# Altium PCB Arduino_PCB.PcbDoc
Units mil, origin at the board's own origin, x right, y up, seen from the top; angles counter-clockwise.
Board outline 2700 x 2100 mil, 2 copper layers (Top Layer, Bottom Layer), stack 44.685 mil thick; 55 components, 50 nets, 239 pads, 59 vias.
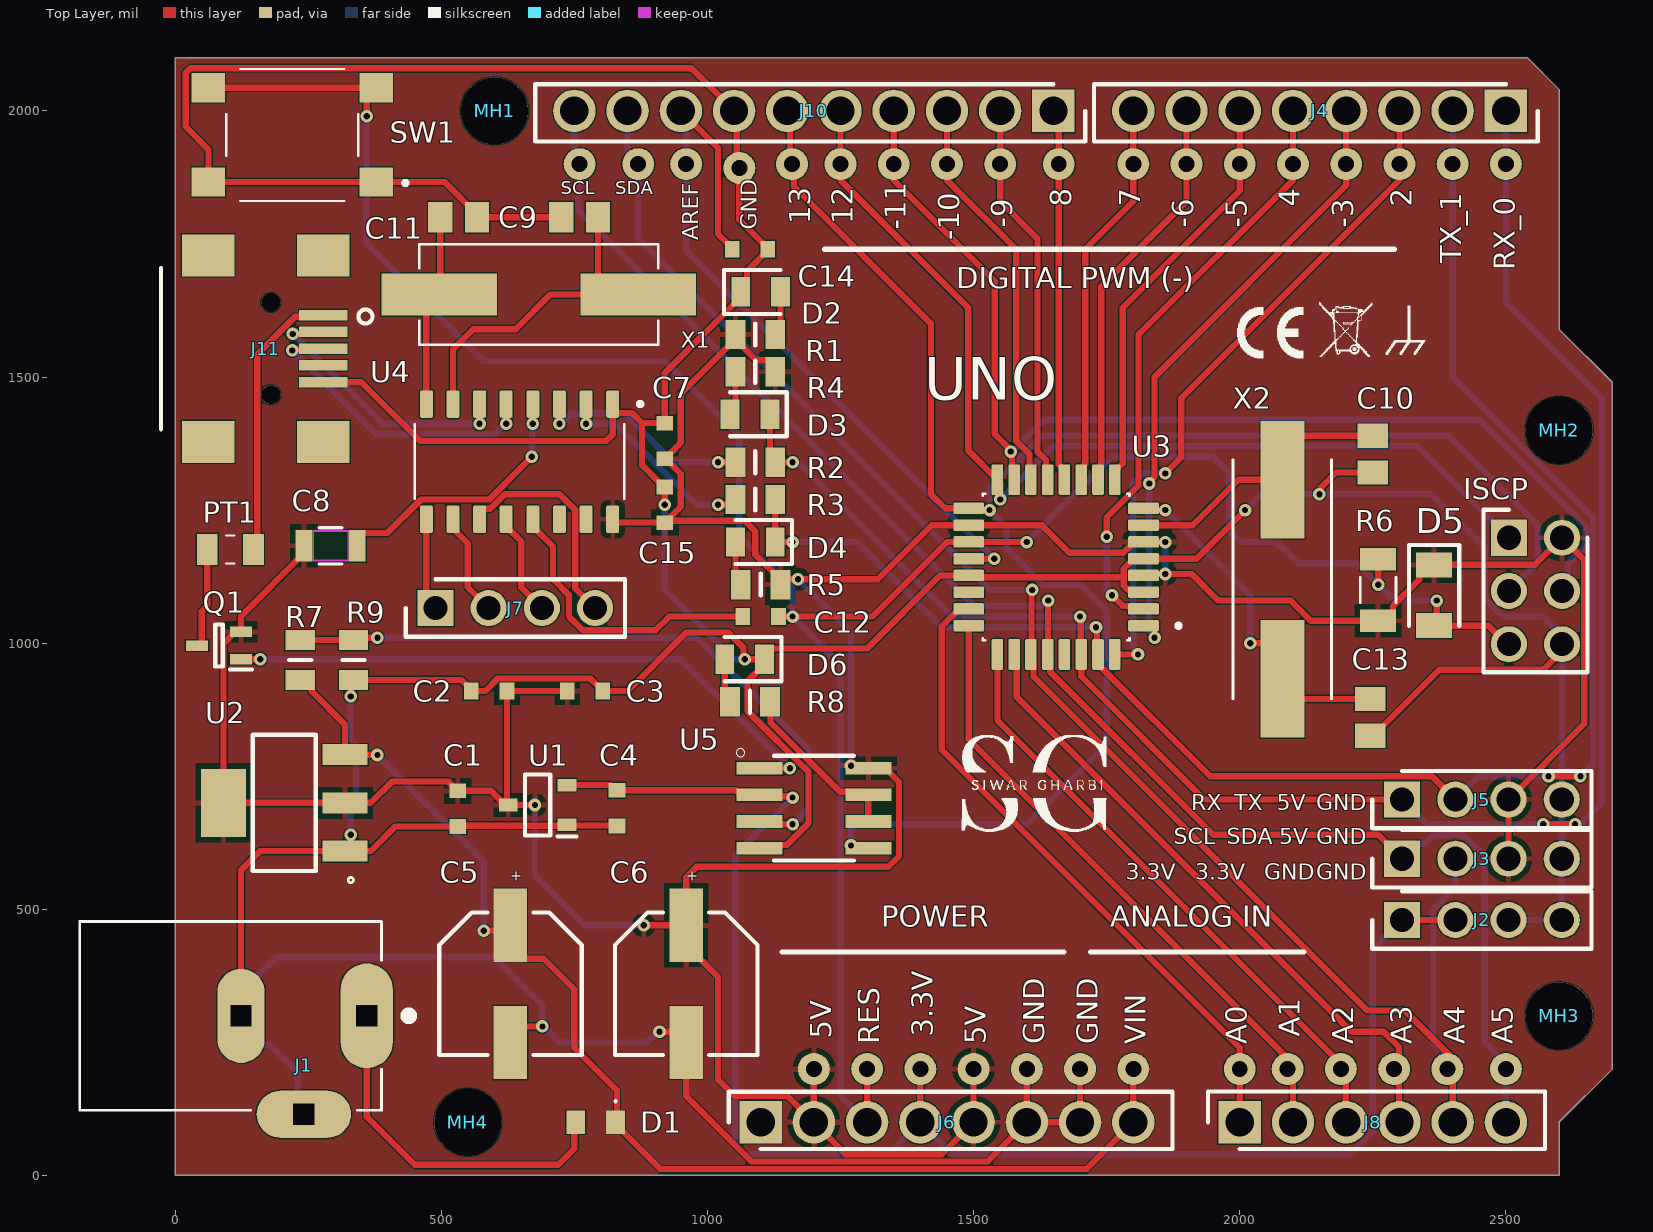
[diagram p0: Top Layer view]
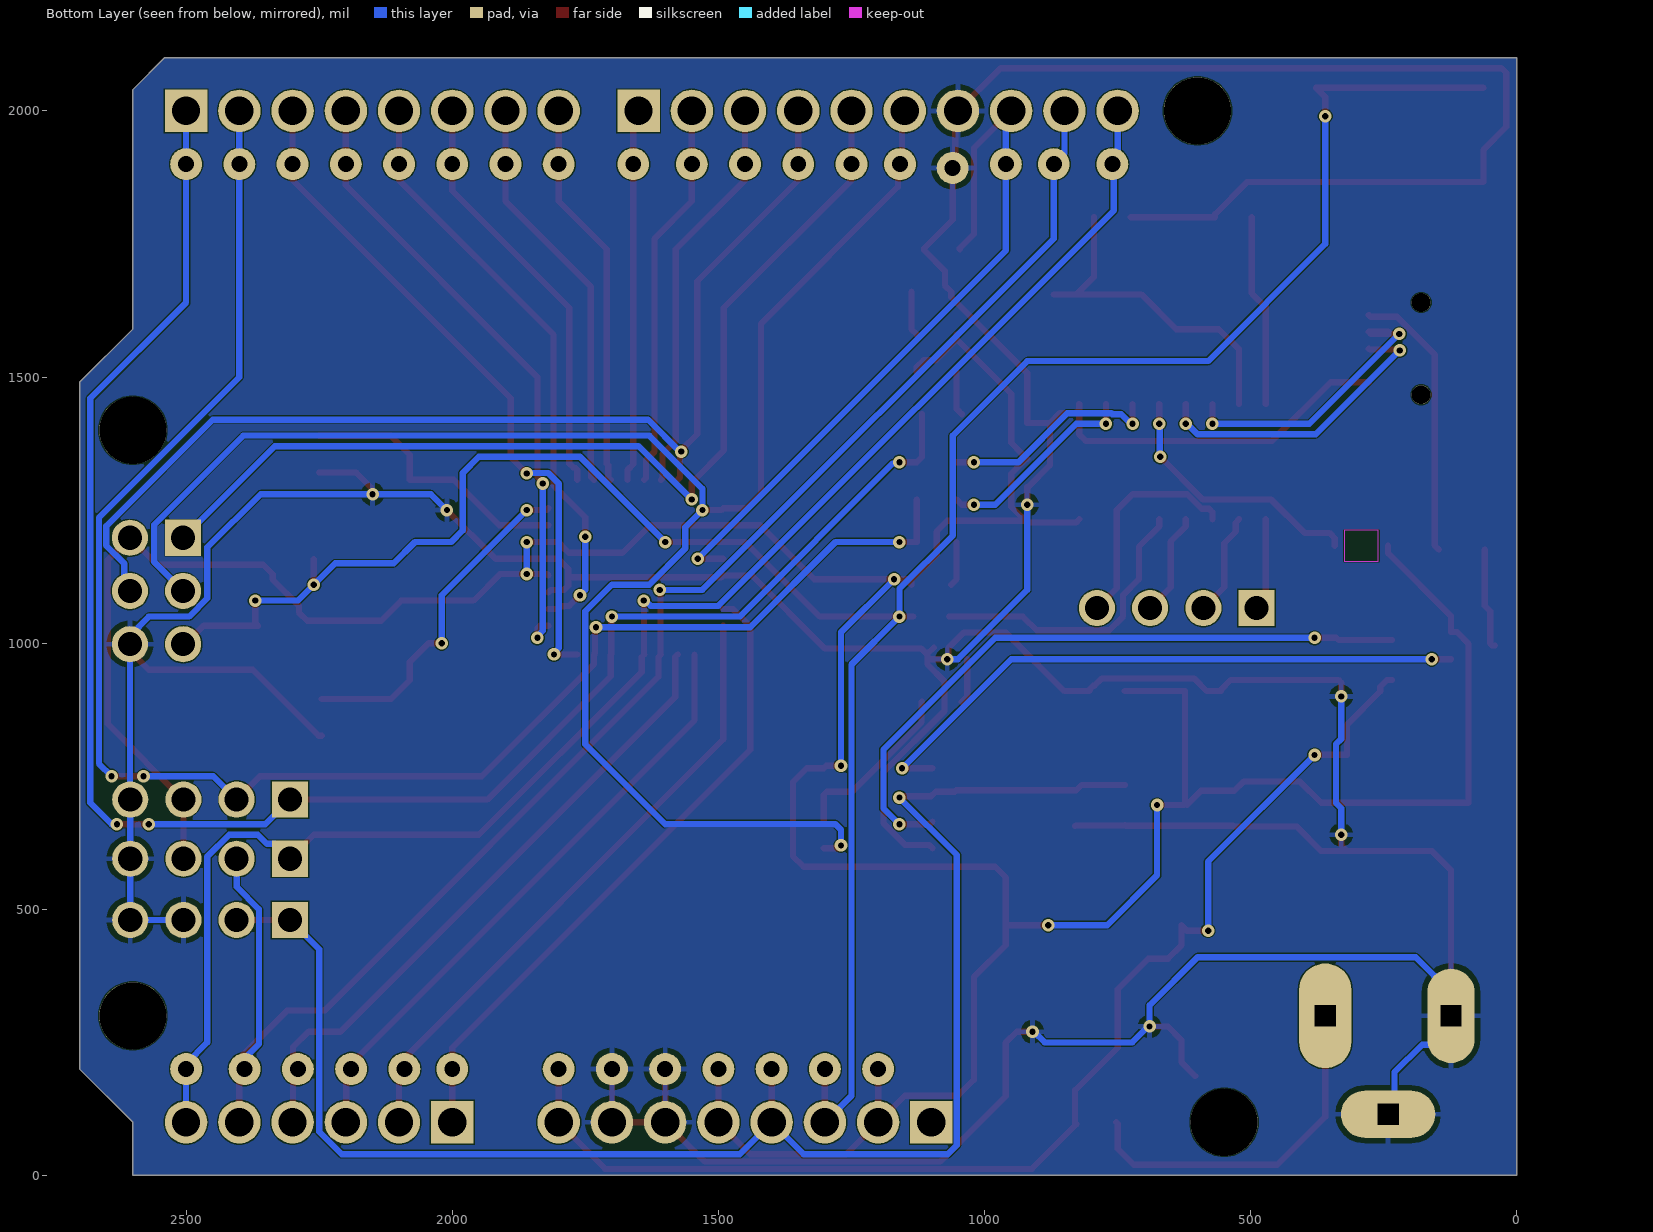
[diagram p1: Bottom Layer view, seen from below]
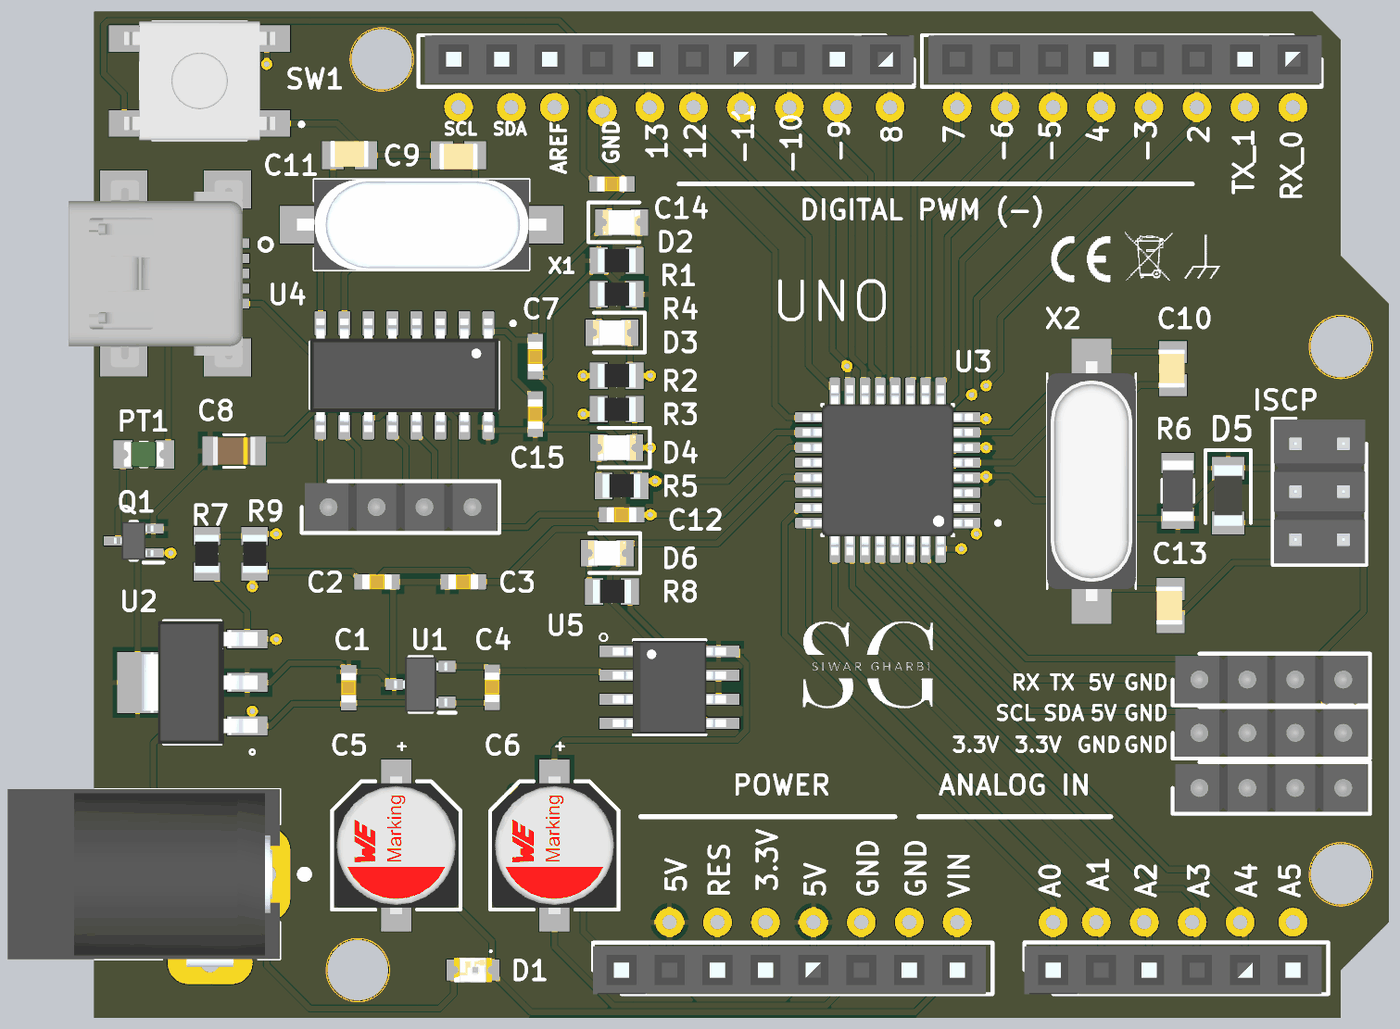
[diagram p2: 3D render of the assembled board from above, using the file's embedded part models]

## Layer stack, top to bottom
Top Solder: solder mask 62.992, SM-001, Dk 4
Top Layer: signal copper 1.378
Dielectric 2: core 41.929, FR-4, Dk 4.8
Bottom Layer: signal copper 1.378
Bottom Solder: solder mask 62.992, SM-001, Dk 4

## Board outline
0,0 2600,0 2600,100 2700,200 2700,1490 2600,1590 2600,2040 2540,2100 0,2100

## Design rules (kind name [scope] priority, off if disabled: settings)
Clearance [All] p1: gap=2 ignorepadtopadclearanceinfootprint=FALSE
ComponentClearance [All] p1: gap=3.94 collisioncheckmode=3 verticalgap=7.87 showdistances=FALSE
HoleSize [All] p1: absolutevalues=TRUE maxlimit=138 minlimit=7.87 maxpercent=80.000 minpercent=20.000
HoleToHoleClearance [All] p1: gap=11.81 allowstackedmicrovias=TRUE
MinimumSolderMaskSliver [All] p1: minsoldermaskwidth=0.07
PolygonConnect [All] p1: connectstyle=Relief reliefconductorwidth=10 reliefentries=4 polygonreliefangle="90 Angle" airgapwidth=10
RoutingVias [All] p1: holewidth=11.81 width=23.62 viastyle="Through Hole" minholewidth=11.81 minwidth=23.62 maxholewidth=11.81 maxwidth=23.62
SilkToSilkClearance [All] p1: silktosilkclearance=0
SilkToSolderMaskClearance [IsPad] p1: minsilkscreentomaskgap=0 clearancetoexposedcopper=TRUE
SolderMaskExpansion [All] p1: expansion=1.5 istentingtop=FALSE
Width [All] p1: maxlimit=39.37 minlimit=11.81 preferedwidth=11.81
24 further rules are at their usual default settings.

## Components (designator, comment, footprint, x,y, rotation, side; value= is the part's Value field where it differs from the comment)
C1 "100nF" WCAP-CSGP_0603_L1.6W0.8H0.8_Wave 531,689.11 r90 top
C2 "100nF" WCAP-CSGP_0603_L1.6W0.8H0.8_Wave 590,910 r0 top
C3 "100nF" WCAP-CSGP_0603_L1.6W0.8H0.8_Wave 770,910 r0 top
C4 "100nF" WCAP-CSGP_0603_L1.6W0.8H0.8_Wave 830,690 r90 top
C5 "47uF" WCAP-ASLI_D6.3H7.7 630,360 r90 top
C6 "47uF" WCAP-ASLI_D6.3H7.7 960,360 r90 top
C7 "100nF" WCAP-CSGP_0603_L1.6W0.8H0.8_Wave 920,1380 r90 top
C8 "10n" CAP_C0805_VEN-M 292,1183 r180 top
C9 "22pF" CAPC2012X140N 760,1800 r0 top
C10 "22pF" CAPC2012X140N 2250,1355 r270 top
C11 "22pF" CAPC2012X140N 532.55,1800 r180 top
C12 "100nF" WCAP-CSGP_0603_L1.6W0.8H0.8_Wave 1100,1050 r0 top
C13 "22pF" CAPC2012X140N 2245,860.55 r270 top
C14 "100nF" WCAP-CSGP_0603_L1.6W0.8H0.8_Wave 1080,1740 r0 top
C15 "100nF" WCAP-CSGP_0603_L1.6W0.8H0.8_Wave 920,1260 r270 top
D1 "Infrared, 1.4V, 140°" WL-SICW_0805_L2W1.3H0.8 790,100 r180 top
D2 "Green LED" LEDC2012X80N 1100,1660 r0 top
D3 "Green LED" LEDC2012X80N 1080,1430 r180 top
D4 "Green LED" LEDC2012X80N 1090,1190 r180 top
D5 "CD1206-S01575" DIOC3215X95N 2365,1090 r270 top
D6 "Green LED" LEDC2012X80N 1070,970 r180 top
ISCP "3X2 Male" HDRV6W67P254_2X3_762X483X858P 2505.51,1198.1 r270 top (schematic designator J9)
J1 "PJ-002A" CUI_PJ-002A 360,300 r180 top locked
J2 "4X1_Male" HDRV4W95P0X254_1X4_1016X254X854P 2305,480 r0 top
J3 "4X1_Male" HDRV4W95P0X254_1X4_1016X254X854P 2305,595 r0 top
J4 "8X1 Female" RHDR8W80P0X254_1X8_2082X254X850P 2500,2000 r180 top
J5 "4X1_Male" HDRV4W95P0X254_1X4_1016X254X854P 2305,706.18 r0 top
J6 "8X1 Female" RHDR8W80P0X254_1X8_2082X254X850P 1100,100 r0 top
J7 "4X1_Male" HDRV4W95P0X254_1X4_1016X254X854P 489,1066 r0 top
J8 "6X1 Female" RHDR6W80P0X254_1X6_1574X254X870P 2000,100 r0 top
J10 "10X1 Female" RHDR10W80P0X254_1X10_2590X254X850P 1650,2000 r180 top
J11 "USB Connector" 1734035-2USB 180,1466.77 r0 top
MH1 "MH_NP_3.2mm" MH_NP_3.2mm#1 600,1980 r0 top
MH2 "MH_NP_3.2mm" MH_NP_3.2mm#2 2600,1400 r0 top
MH3 "MH_NP_3.2mm" MH_NP_3.2mm#2 2600,300 r0 top
MH4 "MH_NP_3.2mm" MH_NP_3.2mm#2 550,100 r0 top
PT1 "500mA" 0ZCK0050AF2E 103.69,1176 r180 top
Q1 "SI1317DL-T1-GE3" SOT65P210X110-3N 82.44,995.59 r180 top
R1 "1K" RESC2012X60N 1090,1580 r0 top
R2 "1K" RESC2012X60N 1090,1340 r0 top
R3 "1K" RESC2012X60N 1090,1270 r0 top
R4 "1K" RESC2012X60N 1090,1510 r180 top
R5 "1K" RESC2012X60N 1100,1110 r180 top
R6 "10 Ohm" RESC3216X70N 2260,1100 r270 top
R7 "10K" RESC2012X60N 235,968.4 r90 top
R8 "1K" RESC2012X60N 1080,890 r180 top
R9 "10K" RESC2012X60N 335,968.4 r90 top
SW1 "B3FS-1000" B3FS1000 220,1955 r0 top
U1 "XC6206P332MR-G" SOT95P280X130-3N 681,696 r180 top
U2 "NCP1117ST50T3G" SOT230P700X180-4N 205,700 r180 top
U3 "ATMEGA328P-AU" QFP80P900X900X120-32N 1655,1143 r180 top
U4 "CH340G" SOIC127P600X180-16N 647,1341 r270 top
U5 "LM358DR2G" SOIC127P600X175-8N 1200,690 r0 top
X1 "12MHz" XTAL_ECS-120-S-5PX-TR 682.99,1655 r180 top
X2 "16MHZ" XTAL_ABLS-9.216MHZ-B4-T 2080,1120 r270 top

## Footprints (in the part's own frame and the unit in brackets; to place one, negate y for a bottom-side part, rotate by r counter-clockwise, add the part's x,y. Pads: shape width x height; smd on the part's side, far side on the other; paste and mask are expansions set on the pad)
0ZCK0050AF2E [mm]
  rect 1x1.5 smd: 1(-1.1,0) 2(1.1,0)
  silkscreen extent -0.2,-0.67 0.2,0.67, body extent -1.07,-0.67 1.07,0.67, height 1.26
1734035-2USB [mm]
  rect 2.3x0.5 smd: 1(2.5,3.8) 2(2.5,3) 3(2.5,2.2) 4(2.5,1.4) 5(2.5,0.6)
  rect 2.5x2 smd: 6(2.5,-2.25) 7(-3,-2.25) 8(-3,6.65) 9(2.5,6.65)
  round 0.9 hole 0.9 unplated: 10(0,4.4) 11(0,0)
  silkscreen extent -5.25,-1.65 4.85,6.05, body extent -5.89,-2.76 3.31,7.14, height 4.14
B3FS1000 [mm]
  rect 1.6x1.4 smd: 1(4,-2.25) 2(-4,-2.25) 3(4,2.25) 4(-4,2.25)
  silkscreen extent -3.15,-3.15 5.5,3.15, body extent -4,-3.15 4,3.15, height 3
CAP_C0805_VEN-M [mil]
  rect 32x60 smd paste+0 mask+0: 1(-50,0) 2(50,0)
  Top Layer keep-out region: -32,-27 -32,27 32,27 32,-27
  Keep-Out Layer region: -32,-29 -32,29 32,29 32,-29
  silkscreen extent -22,-34 22,34, body extent -44,-29 44,29, height 12
CAPC2012X140N [mm]
  rect 1.16x1.47 smd: 1(-0.875,0) 2(0.875,0)
  body extent -1.02,-0.76 1.02,0.64, height 1.28
CUI_PJ-002A [mm]
  oval 2.5x5 hole 1 square: 1(0,0)
  oval 2.25x4.5 hole 1 square: 2(6,0)
  oval 4.5x2.25 hole 1 square: 3(3,4.7)
  silkscreen extent -2.2,-4.5 13.7,4.5, body extent -0.7,-4.5 13.7,4.9, height 11
DIOC3215X95N [mm]
  rect 1.2x1.7 smd: 1(-1.45,0) 2(1.45,0)
  silkscreen extent -2.4,-1.2 1.45,1.2, body extent -1.6,-0.75 1.6,0.75, height 0.95
HDRV4W95P0X254_1X4_1016X254X854P [mm]
  rect 1.725x1.725 / inner round 1.725 / far side rect 1.725x1.725 hole 1.15: 1(0,0)
  round 1.725 hole 1.15: 2(2.54,0) 3(5.08,0) 4(7.62,0)
  silkscreen extent -1.42,-1.37 9.04,1.37, body extent -1.27,-1.27 8.89,1.27, height 8.54
HDRV6W67P254_2X3_762X483X858P [mm]
  rect 1.725x1.725 hole 1.15: 1(0,0)
  round 1.725 hole 1.15: 2(0,2.54) 3(2.54,0) 4(2.54,2.54) 5(5.08,0) 6(5.08,2.54)
  silkscreen extent -1.34,-1.21 6.42,3.75, body extent -1.27,-1.14 6.35,3.68, height 8.58
LEDC2012X80N [mm]
  rect 0.9x1.4 smd: 1(-0.95,0) 2(0.95,0)
  silkscreen extent -1.75,-1.05 0.95,1.05, body extent -1,-0.65 1,0.65, height 0.81
MH_NP_3.2mm#1 [mm]
  round 3.2 hole 3.2 mask+0.102: 1(0,0.508)
MH_NP_3.2mm#2 [mm]
  round 3.2 hole 3.2 mask+0.102: 1(0,0)
QFP80P900X900X120-32N [mm]
  rrect25% 1.47x0.55 smd: 1(-4.17,2.8) 2(-4.17,2) 3(-4.17,1.2) 4(-4.17,0.4) 5(-4.17,-0.4) 6(-4.17,-1.2) 7(-4.17,-2) 8(-4.17,-2.8) 17(4.17,-2.8) 18(4.17,-2) 19(4.17,-1.2) 20(4.17,-0.4) 21(4.17,0.4) 22(4.17,1.2) 23(4.17,2) 24(4.17,2.8)
  rrect25% 0.55x1.47 smd: 9(-2.8,-4.17) 10(-2,-4.17) 11(-1.2,-4.17) 12(-0.4,-4.17) 13(0.4,-4.17) 14(1.2,-4.17) 15(2,-4.17) 16(2.8,-4.17) 25(2.8,4.17) 26(2,4.17) 27(1.2,4.17) 28(0.4,4.17) 29(-0.4,4.17) 30(-1.2,4.17) 31(-2,4.17) 32(-2.8,4.17)
  silkscreen extent -5.94,-3.5 3.5,3.5, body extent -4.5,-4.5 4.5,4.5, height 1.2
RESC2012X60N [mm]
  rect 0.95x1.4 smd: 1(-0.95,0) 2(0.95,0)
  silkscreen extent 0,-0.53 0,0.53, body extent -1,-0.63 1,0.63, height 0.6
RESC3216X70N [mm]
  rect 1.08x1.72 smd: 1(-1.47,0) 2(1.47,0)
  silkscreen extent -0.61,-0.85 0.61,0.85, body extent -1.6,-0.8 1.6,0.8, height 0.71
RHDR6W80P0X254_1X6_1574X254X870P [mm]
  rect 2.025x2.025 hole 1.35: 1(0,0)
  round 2.025 hole 1.35: 2(2.54,0) 3(5.08,0) 4(7.62,0) 5(10.16,0) 6(12.7,0)
  silkscreen extent -1.52,-1.27 14.57,1.47, body extent -1.52,-1.27 14.22,1.27, height 8.7
RHDR8W80P0X254_1X8_2082X254X850P [mm]
  rect 2.025x2.025 hole 1.35: 1(0,0)
  round 2.025 hole 1.35: 2(2.54,0) 3(5.08,0) 4(7.62,0) 5(10.16,0) 6(12.7,0) 7(15.24,0) 8(17.78,0)
  silkscreen extent -1.52,-1.27 19.65,1.46, body extent -1.52,-1.27 19.3,1.27, height 8.5
RHDR10W80P0X254_1X10_2590X254X850P [mm]
  rect 2.025x2.025 hole 1.35: 1(0,0)
  round 2.025 hole 1.35: 2(2.54,0) 3(5.08,0) 4(7.62,0) 5(10.16,0) 6(12.7,0) 7(15.24,0) 8(17.78,0) 9(20.32,0) 10(22.86,0)
  silkscreen extent -1.52,-1.27 24.73,1.46, body extent -1.52,-1.27 24.38,1.27, height 8.5
SOIC127P600X175-8N [mm]
  rect 2.2x0.6 smd: 1(-2.6,1.905) 2(-2.6,0.635) 3(-2.6,-0.635) 4(-2.6,-1.905) 5(2.6,-1.905) 6(2.6,-0.635) 7(2.6,0.635) 8(2.6,1.905)
  silkscreen extent -3.7,-2.5 1.9,2.85, body extent -3,-2.45 3,2.45, height 1.75
SOIC127P600X180-16N [mm]
  rrect25% 1.31x0.62 smd: 1(-2.75,4.445) 2(-2.75,3.175) 3(-2.75,1.905) 4(-2.75,0.635) 5(-2.75,-0.635) 6(-2.75,-1.905) 7(-2.75,-3.175) 8(-2.75,-4.445) 9(2.75,-4.445) 10(2.75,-3.175) 11(2.75,-1.905) 12(2.75,-0.635) 13(2.75,0.635) 14(2.75,1.905) 15(2.75,3.175) 16(2.75,4.445)
  silkscreen extent -2.85,-5 1.78,5.85, body extent -3,-5 3,5, height 1.8
SOT65P210X110-3N [mm]
  rect 1.05x0.5 smd: 1(-1.05,0.65) 2(-1.05,-0.65) 3(1.05,0)
  silkscreen extent -1.58,-1 0.18,1.15, body extent -1.05,-1 1.05,1, height 1.1
SOT95P280X130-3N [mm]
  rect 0.9x0.6 smd: 1(-1.4,0.95) 2(-1.4,-0.95) 3(1.4,0)
  silkscreen extent -1.85,-1.45 0.6,1.5, body extent -1.4,-1.45 1.4,1.45, height 1.3
SOT230P700X180-4N [mm]
  rect 2.15x1 smd: 1(-2.9,2.3) 2(-2.9,0) 3(-2.9,-2.3)
  rect 2.15x3.25 smd: 4(2.9,0)
  silkscreen extent -3.3,-3.25 1.5,3.81, body extent -3.49,-3.25 3.64,3.25, height 1.81
WCAP-ASLI_D6.3H7.7 [mm] "Aluminium Electrolytic V-Chip SMT Capacitors, 6.3x7.7mm"
  rect 3.5x1.6 smd: 1(2.8,0) 2(-2.8,0)
  silkscreen extent -3.4,-3.4 3.4,3.4, body extent -3.65,-3.3 3.65,3.3, height 7.7
WCAP-CSGP_0603_L1.6W0.8H0.8_Wave [mm] "Ceramic Capacitors, 0603, body 1.6x0.8mm"
  rect 0.7x0.8 smd: 1(-0.85,0) 2(0.85,0)
  body extent -0.8,-0.4 0.8,0.4, height 0.8
WL-SICW_0805_L2W1.3H0.8 [mm] "SMT Infrared Chip LED Waterclear, body 2x1.3mm"
  rect 0.9x1.1 smd: 1(-0.95,0) 2(0.95,0)
  silkscreen extent -1,-1.05 -0.9,-0.95, body extent -1,-0.65 1,0.65, height 0.8
XTAL_ABLS-9.216MHZ-B4-T [mm]
  rect 5.6x2.1 smd: 1(-4.75,0) 2(4.75,0)
  silkscreen extent -5.7,-2.35 5.7,2.35, body extent -6.35,-2.35 6.35,2.35, height 4.06
XTAL_ECS-120-S-5PX-TR [mm]
  rect 5.5x2 smd: 1(-4.75,0) 2(4.75,0)
  silkscreen extent -5.7,-2.4 5.7,2.4, body extent -6.6,-2.39 6.6,2.41, height 4.31

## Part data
C1 C2 C3 C4 C7 C12 C14 C15: library part "Capacitor 885012206071R", "WCAP-CSGP Multilayer Ceramic Chip Capacitor, General Purpose, size 0603, X7R, 100nF, 25VDC", Capacitance Tolerance=+/-10%, Case/Size Code=0603, Insulation Resistance=5GOhm, Manufacturer="Wurth Elektronik", Manufacturer Part Number=885012206071R, Operating Temperature Max=125°C, Operating Temperature Min=-55°C, Rated Voltage (DC)=25V
C5 C6: library part "Capacitor 865080443007", "WCAP-ASLI Aluminum Electrolytic Capacitor, V-Chip, D6.3 x H5.5mm, 47uF, 25V", Capacitance Tolerance=+/-20%, Leakage Current=11.75uA, Manufacturer="Wurth Elektronik", Manufacturer Part Number=865080443007, Operating Temperature Max=105°C, Operating Temperature Min=-55°C, Rated Voltage (DC)=25V, Ripple Current=220mA
C8: library part "Cap 0805X7R500-104KNE", "0.1 µF ±10% 50V Ceramic Capacitor X7R 0805 (2012 Metric)", Mfr_Name=Venkel
C9 C10 C11 C13: library part C0805C220J5GACTU, "22pF Â±5% 50V Ceramic Capacitor C0G, NP0 0805 _2012 Metric_", Package="0805 Kemet"
D1: library part 15408085BA400, "WL-SICW SMT Chip LED Infrared Waterclear, size 0805, Infrared, 1.4V, 140°", Case/Size Code=0805, Emitting Color=Infrared, Forward Voltage=1.4V, Forward Voltage Max=2V, Manufacturer="Wurth Elektronik", Operating Temperature Max=85°C, Operating Temperature Min=-40°C
D2 D3 D4 D6: library part "LED Green _R971-KN-1", "Standard LEDs - SMD Green, 570nm 26mcd, 20mA", Manufacturer_Name="ams OSRAM", Manufacturer_Part_Number="LG R971-KN-1", Mouser Part Number=720-LGR971-KN-1
D5: "Diode Switching 100V 0.15A 4ns SMD1206 Bourns CD1206-S01575 Switching Diode, 150mA, 100V, 4ns, 2-Pin 1206", Manufacturer_Name=Bourns, Mouser Part Number=652-CD1206-S01575
ISCP: library part "Con 3X2 67997-206HLF", "Connector", Manufacturer_Name=Amphenol, Manufacturer_Part_Number=67997-206HLF, Mouser Part Number=649-67997-206HLF
J1: "2.0 x 6.5 mm, 2.5 A, Horizontal, Through Hole, Dc Power Jack Connector", Package=None
J2 J3 J5 J7: library part "Con 4X1 61300411121", "WR-PHD 2.54mm Pin Header THT Straight 4p Wurth Elektronik WR-PHD Series, Series Number 6130, 2.54mm Pitch 4 Way 1 Row Straight PCB Header, Solder Termination", Manufacturer_Name="Wurth Elektronik", Manufacturer_Part_Number=61300411121, Mouser Part Number=710-61300411121
J4 J6: library part "Con 8X1 PPTC081LFBN-RC", "Connector", Manufacturer_Name=Sullins, Manufacturer_Part_Number=PPTC081LFBN-RC
J8: library part "Con 6X1 PPTC061LFBN-RC", "Connector", Manufacturer_Name=Sullins, Manufacturer_Part_Number=PPTC061LFBN-RC
J10: library part "Con 10X1 PPTC101LFBN-RC", "10 Position Header Connector 0.100\" (2.54mm) Through Hole Tin", Manufacturer_Name=Sullins, Manufacturer_Part_Number=PPTC101LFBN-RC
J11: library part "Con USB 1734035-4", "Conn Mini USB 2.0 Type B RCP 5 POS 0.8mm Solder RA SMD 5 Terminal 1 Port Automotive T/R", Arrow Part Number=1734035-4, Manufacturer_Name="TE Connectivity", Mouser Part Number=571-1734035-4
MH1 MH2 MH3 MH4: "Mounting Hole 3.2mm"
PT1: library part "PT 0ZCK0050AF2E", "PTC Resettable Fuse 0.5A(hold) 1A(trip) 9VDC 100A 0.5W 0.1s 0.15Ohm SMD Solder Pad 0805 2.3 X 1.5 X 0.9mm Automotive", Manufacturer_Name=Bel, Manufacturer_Part_Number=0ZCK0050AF2E
Q1: "Vishay SI1317DL-T1-GE3 P-channel MOSFET Transistor, 1.1 A, -20 V, 3-Pin SOT-323", Manufacturer_Name=Vishay, Mouser Part Number=78-SI1317DL-T1-GE3
R1 R2 R3 R4 R5 R8: library part "Res RC0805FR-071KL", "YAGEO - RC0805FR-071KL - SMD Chip Resistor, 1 kohm, +/- 1%, 125 mW, 0805 [2012 Metric], Thick Film, General Purpose", Manufacturer_Name=YAGEO, Manufacturer_Part_Number=RC0805FR-071KL, Mouser Part Number=603-RC0805FR-071KL
R6: library part "Res FCR1206J10R", "Res 1206 10 Ohm 5% 1/8W Â±500ppm/Â°C Molded SMD SMD T/R", Package=1206, Power_Rating=".125 W", Resistance=10, Tolerance=5%
R7 R9: library part "Res RC0805FR-0710KL", "YAGEO - RC0805FR-0710KL - SMD Chip Resistor, 10 kohm, +/- 1%, 125 mW, 0805 [2012 Metric], Thick Film, General Purpose", Manufacturer_Name=YAGEO, Manufacturer_Part_Number=RC0805FR-0710KL, Mouser Part Number=603-RC0805FR-0710KL
SW1: library part Switch, "Switch Tactile N.O. SPST Flat Plunger Gull Wing 0.05A 24VDC 0.98N SMD Bag", Manufacturer_Name="Omron Electronics", Mouser Part Number=653-B3FS-1000
U1: library part "Voltage Regulators", "LDO Voltage Regulators 1uA Low Quiescent 3 Terminal, Low ESR Cap. Compatible, Voltage Regulator", Manufacturer_Name=Torex, Mouser Part Number=865-XC6206P332MR-G
U2: library part "Voltage Regulator NCP1117ST50T3G", "Linear Voltage Regulator IC 1 Output 1A SOT-223", Package="TO-261-4 ON Semiconductor"
U3: "AVR AVRÂ® ATmega Microcontroller IC 8-Bit 20MHz 32KB (16K x 16) FLASH 32-TQFP (7x7)", Package="TQFP-32 Microchip"
U4: "USB Interface Integrated Circuit", Package=None
U5: library part "AOP LM358DR2G", "General Purpose Amplifier 2 Circuit - 8-SOIC", Package="SOIC-8 ON Semiconductor"
X1: library part "Crystal 12MHz - ECS-120-S-5PX-TR", "12MHz Â±30ppm Crystal Series 50 Ohms HC-49/US", Package="HC49/US ECS International"
X2: library part ABLS-9.216MHZ-B4-T, "HC/49US (AT49) SMD LOW PROFILE CRYSTAL", Package="HC-49/US Abracon LLC"

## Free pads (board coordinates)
  round 60 hole 30: 3(760,1900) 3(870,1900) 3(960,1900) 3(1060,1892.72) 3(1158.86,1900) 3(1250,1900) 3(1350,1900) 3(1450,1900) 3(1550,1900) 3(1660,1900) 3(1800,1900) 3(1900,1900) 3(2000,1900) 3(2100,1900) 3(2190,200) 3(2200,1900) 3(2300,1900) 3(2400,1900) 3(2500,1900) 4(2000,200) 5(2090,200) 6(2290,200) 7(2390,200) 8(2500,200) 9(1800,200) 10(1700,200) 11(1600,200) 12(1500,200) 13(1400,200) 14(1300,200) 15(1200,200)

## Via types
v1: diameter 23.62, hole 11.81, Top Layer to Bottom Layer, 59 vias

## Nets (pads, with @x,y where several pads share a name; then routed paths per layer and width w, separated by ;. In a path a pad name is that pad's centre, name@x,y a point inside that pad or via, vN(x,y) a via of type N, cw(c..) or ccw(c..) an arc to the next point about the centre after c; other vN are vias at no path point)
+3V3: C4.2 J2.1 J2.2 J6.4 pad.13 U1.2 U5.2 | length 3023.7
  Top Layer w11.81: U1.2 818.09,733.4 828.03,723.46 C4.2 1053.32,723.46 1055.88,720.91 1091.73,720.91 U5.2 1100.38,712.26 1157.74,712.26 v1(1160,710) ; J6.4 pad.13 ; J2.1 J2.2
  Bottom Layer w11.81: v1(1160,710) 1052.23,602.23 1052.23,56.86 1069.1,40 1340,40 J6.4 1460,40 2207.55,40 2250,82.45 2250,425 J2.1
+5V: C1.2 C2.2 C3.1 C6.1 C7.1 C8.2 C15.2 D5.1 ISCP.2 J3.3 J5.3 J6.2 J6.5 pad.12 pad.15 Q1.2 R1.1 R4.1 R5.1 R6.2 U1.3 U2.2 U2.4 U3.4 U3.6 U3.18 U4.16 U5.8 | length 7535.5
  Top Layer w11.81: C8.2 242,1169 123.78,1050.78 Q1.2 112.95,1021.18 90.83,999.05 U2.4 U2.2 367.4,700 407.4,740 513.57,740 C1.2 593.4,722.57 U1.3@619.98,696 ; U1.3@623.46,699.49 C2.2 C3.1 ; U1.3 v1(676,696) ; U4.16 828.2,1226.54 C15.2 923.46,1230 C15.2@925.43,1230 ; v1(880.24,470.24) C6.1 ; C7.1 C7.1@921.97,1346.53 ; R1.1 R1.1@1052.6,1571.14 ; R4.1 1127.4,1518.86 1114.61,1531.65 1092.09,1531.65 R1.1@1052.6,1571.14 ; pad.15 J6.2 ; v1(1269.72,770) 1297.36,770 U5.8 1333.86,765 1360,738.86 1360,600 1340,580 980,580 960,560 C6.1 ; pad.12 J6.5 1440,40 1260,40 J6.2 ; U3.4 1821.92,1130 v1(1860,1130) 1910,1130 1960,1080 2095.75,1080 2133.62,1042.13 R6.2 2272.6,1042.13 2287.95,1057.48 2287.95,1070.04 2337.44,1119.53 2337.44,1129.37 2355.16,1147.09 D5.1 2554.5,1147.09 ISCP.2 2647.37,1156.24 2647.37,848.56 J5.3 J3.3 ; v1(1860,1190) 1859.76,1190.24 U3.6 1801.06,1190.24 1796.14,1185.32 1796.14,1184.4 1789.22,1177.48 1788.55,1177.48 1781.07,1170 1680,1170 1628.26,1221.74 U3.18 1421.74,1221.74 1320,1120 v1(1170,1120) 1147.4,1120 R5.1 1137.4,1118.86 1090,1166.26 1090,1210 1070,1230 C15.2@925.43,1230 ; C7.1@921.97,1346.53 950,1318.5 950,1256.54 929.84,1236.38 929.84,1234.41 C15.2@925.43,1230 ; C7.1@921.97,1346.53 929.84,1354.41 929.84,1356.38 950,1376.53 950,1468.54 R1.1@1052.6,1571.14 ; C6.1 960,432.83 1020,372.83 1020,180 1050,150 1150,150 J6.2
  Bottom Layer w11.81: v1(676,696) 676,564 769.76,470.24 v1(880.24,470.24) ; v1(1170,1120) 1269.72,1020.28 v1(1269.72,770) ; v1(1860,1130) v1(1860,1190)
AD0: J8.1 pad.4 U3.23 | length 1227.9
  Top Layer w11.81: U3.23 1472.72,1064.26 1440,1031.54 1440,800 2000,240 J8.1
AD1: J8.2 pad.5 U3.24 | length 1185.1
  Top Layer w11.81: U3.24 1490.83,819.17 2100,210 J8.2
AD2: J8.3 pad.3@2190,200 U3.25 | length 1150.2
  Top Layer w11.81: U3.25 1544.76,855.24 2199.34,200.66 2199.34,100.66 J8.3
AD3: J8.4 pad.6 U3.26 | length 1212.8
  Top Layer w11.81: U3.26 1581.18,973.9 1581.18,898.82 2210,270 2270,270 2299.34,240.66 2299.34,200.66 J8.4@2299.34,100.66
AD4/SDA: J3.2 J8.5 J10.9 pad.3@870,1900 pad.7 U3.27 | length 3059.6
  Top Layer w11.81: v1(1610,1100) 1608.88,1098.88 1608.88,979.95 U3.27 1612.68,973.9 1612.68,936.85 2239.53,310 2310,310 2392.69,227.31 2392.69,207.31 2400,200 J8.5
  Bottom Layer w11.81: J10.9 850,1920.33 870,1900.33 870,1760 1530,1100 v1(1610,1100) ; pad.7@2400,200 2400,210 2363.14,246.86 2363.14,500.31 2405,542.17 J3.2
AD5/SCL: J3.1 J8.6 J10.10 pad.3@760,1900 pad.8 U3.28 | length 3033.8
  Top Layer w11.81: v1(1640,1080) 1639.63,1079.63 1639.63,979.2 U3.28 1644.17,973.9 1644.17,945.83 1950,640 2260,640 J3.1
  Bottom Layer w11.81: J10.10 750,1910 757.31,1902.69 757.31,1812.69 1500,1070 1627.18,1070 1637.18,1080 v1(1640,1080) ; J3.1 2333.05,623.05 2348.19,623.05 2365.14,640 2419.2,640 2460,599.2 2460,250 2500,210 J8.6
AREF: C14.1 J10.8 pad.3@960,1900 U3.20 | length 1433
  Top Layer w11.81: J10.8 1020,1930 1020,1768.5 1046.54,1741.97 C14.1 ; U3.20 v1(1538.75,1158.75)
  Bottom Layer w11.81: J10.8 960,1990 960,1737.5 v1(1538.75,1158.75)
CTS: J7.1 U4.9 | length 173.8
  Top Layer w11.81: U4.9 472,1083 J7.1
DC-JACK: D1.2 J1.1 | length 680.8
  Top Layer w11.81: J1.1 360,110 450,20 720,20 750,50 750,97.4 D1.2
DCD: J7.3 U4.12 | length 194.5
  Top Layer w11.81: U4.12 622,1219.15 650,1191.15 650,1105 J7.3
DSR: J7.2 U4.10 | length 194.5
  Top Layer w11.81: U4.10 528.3,1226.43 528.3,1209.7 550,1188 550,1105 J7.2
Fuse_5V: PT1.2 Q1.3 | length 191.3
  Top Layer w11.81: Q1.3 46.06,995.59 50,999.53 50,1060 60.38,1070.38 PT1.2
GND: C1.1 C2.1 C3.2 C4.1 C5.2 C6.2 C7.2 C9.1 C10.2 C11.1 C13.2 C14.2 C15.1 D2.1 D6.1 ISCP.6 J1.2 J1.3 J2.3 J2.4 J3.4 J5.4 J6.6 J6.7 J10.7 J11.5 pad.3@1060,1892.72 pad.10 pad.11 R9.1 SW1.1 SW1.2 U1.1 U2.1 U3.3 U3.5 U3.21 U4.1 U5.4 | length 12285.1
  Top Layer w11.81: J1.2 123.78,573.78 159.45,609.45 U2.1 ; J11.5 349.61,1490.39 460,1380 810,1380 822,1392 U4.1@822,1438.74 ; v1(330,640) 330,620.27 U2.1 ; v1(330,900) 330,926 R9.1 537.5,931 556.54,911.97 C2.1 582.76,910 606.41,933.65 779.81,933.65 793.62,919.84 795.59,919.84 803.46,911.97 C3.2 850,910 960,1020 1039.05,1020 1067.74,991.31 1067.74,972.26 v1(1070,970) D6.1 ; C5.2@604.41,186.77 630,212.36 C5.2 630,254.41 655.59,280 v1(690,280) ; C9.1 C11.1 567,1806.1 506.68,1866.42 SW1.1 SW1.2 62.52,1927.48 20,1970 20,2071.3 28.7,2080 970,2080 J10.7 1055,1995 1055,1897.72 1060,1892.72 1060,1795.43 1113.46,1741.97 C14.2 1113.46,1738.03 1074.41,1698.98 1074.41,1671.81 D2.1 1062.6,1650.16 920,1507.56 C7.2 877.19,1413.46 ; U4.1 U4.1@822,1438.74 ; C4.1 828.97,657.57 737.15,657.57 U1.1 734.64,657.12 532.48,657.12 C1.1 413.6,655.65 367.4,609.45 U2.1 ; v1(910,270) 939.76,270 C6.2 960,149.1 1082.91,26.19 1525.93,26.19 J6.6@1599.74,100 ; v1(920,1260) C15.1 918.03,1293.46 877.19,1334.31 877.19,1413.46 ; D6.1@1095.59,991.65 1107.4,979.84 D6.1@1107.4,978.19 ; U5.4 1103.54,620.91 1148.79,620.91 1190,662.12 1190,757.88 1075.2,872.68 1075.2,927.96 1107.4,960.16 D6.1 ; pad.11 J6.6 J6.7 pad.10 ; U3.3 1814.93,1100 1790,1100 1782.33,1107.67 1782.33,1123.84 ; v1(2010,1250) 1918.75,1158.75 U3.5 1801.06,1158.75 1782.33,1140.02 1782.33,1123.84 ; 2151.9,1291.9 2180.55,1320.55 C10.2 ; C13.2 2251.1,826.1 2375,950 2570,950 2605.51,985.51 ISCP.6 ; U4.1@822,1438.74 828.3,1432.44 858.22,1432.44 877.19,1413.46 ; D6.1 D6.1@1107.4,978.19 ; D6.1@1107.4,978.19 1119.21,990 1300,990 1437.25,1127.25 U3.21 1494.24,1123.84 1782.33,1123.84
  Bottom Layer w11.81: J1.3 230,126.85 230,193.78 177.96,245.82 159.24,245.82 123.78,281.28 J1.2 123.78,343.78 190,410 600,410 690,320 v1(690,280) 692.82,280 722.82,250 887.18,250 907.18,270 v1(910,270) ; v1(330,640) 330,690 340,700 340,810 330,820 v1(330,900) ; v1(920,1260) 920,1100 1050,970 v1(1070,970) ; v1(2010,1250) 2040.02,1280.02 v1(2149.64,1280.02) 2359.98,1280.02 2460,1180 2460,1084.41 2494.41,1050 2570,1050 2588.98,1031.02 2588.98,1029.81 2605.51,1013.28 ISCP.6 2605.26,997.84 2605.26,706.44 J5.4 J3.4 J2.4 J2.3
IO0/RX: D3.1 J4.1 J5.1 pad.3@2500,1900 R2.2 U3.30 | length 3384
  Top Layer w11.81: D3.1 1117.4,1350 R2.2 v1(1160,1340) ; v1(1700,1050) 1701.12,1048.88 1701.12,979.95 U3.30 1702.24,937.76 1933.82,706.18 J5.1 ; v1(2570,660) v1(2630,660)
  Bottom Layer w11.81: v1(1160,1340) 1162.26,1337.74 1172.26,1337.74 1460,1050 v1(1700,1050) ; J5.1 2351.18,660 v1(2570,660) ; J4.1 2500,1640 2680,1460 2680,700 2640,660 v1(2630,660)
IO1/TX: D4.1 J4.2 J5.2 pad.3@2400,1900 R3.2 U3.31 | length 3218.7
  Top Layer w11.81: R3.2 D4.1 v1(1160,1190) ; v1(1730,1030) 1731.87,1028.13 1731.87,980.7 U3.31 1733.74,960.72 1944.46,750 2361.18,750 J5.2 ; v1(2580,750) v1(2640,750)
  Bottom Layer w11.81: v1(1160,1190) 1280,1190 1440,1030 v1(1730,1030) ; J4.2 2400,1499.74 2663.81,1235.92 2663.81,773.81 v1(2640,750) ; J5.2 2448.82,750 v1(2580,750)
IO2: J4.3 pad.3@2300,1900 U3.32 | length 1318.6
  Top Layer w11.81: U3.32 v1(1808.83,978.83) ; v1(1860,1318.95) 1890,1348.95 1890,1460 2300,1870 J4.3 J4.3@2281.62,2000
  Bottom Layer w11.81: v1(1808.83,978.83) 1808.83,982.02 1800,990.85 1800,1300 1819.72,1319.72 1859.23,1319.72 v1(1860,1318.95)
IO3: J4.4 pad.3@2200,1900 U3.1 | length 1188.1
  Top Layer w11.81: U3.1 1835.08,1032.76 1840,1027.84 v1(1840,1010) ; v1(1830,1300) 1830,1302.82 1840,1312.82 1840,1500 2200,1860 J4.4
  Bottom Layer w11.81: v1(1830,1300) 1830,1023.2 1840,1013.2 v1(1840,1010)
IO4: J4.5 pad.3@2100,1900 U3.2 | length 1129
  Top Layer w11.81: v1(1750,1200) 1750,1236.56 1810,1296.56 1810,1580 2100,1870 J4.5 ; v1(1760,1090) 1780,1070 1789.22,1070 1790.04,1069.18 1796.14,1069.18 1801.06,1064.26 U3.2
  Bottom Layer w11.81: v1(1750,1200) 1750,1100 v1(1760,1090)
IO5: J4.6 pad.3@2000,1900 U3.9 | length 791.8
  Top Layer w11.81: U3.9 1765.24,1325.28 1770.16,1330.21 1773.08,1330.21 1780,1337.12 1780,1630 2000,1850 J4.6
IO6: J4.7 pad.3@1900,1900 U3.10 | length 761.7
  Top Layer w11.81: U3.10 1738.66,1312.1 1738.66,1335.79 1740,1337.12 1740,1670 1900,1830 J4.7
IO7: J4.8 pad.3@1800,1900 U3.11 | length 733.3
  Top Layer w11.81: U3.11 1707.17,1312.1 1707.17,1334.29 1710,1337.12 1710,1740 1800,1830 J4.8
IO8: J10.1 pad.3@1660,1900 U3.12 | length 701.4
  Top Layer w11.81: J10.1 1660,1990 1660,1336.03 1670.75,1325.28 U3.12
IO9: J10.2 pad.3@1550,1900 U3.13 | length 729.8
  Top Layer w11.81: J10.2 1550,1830 1620,1760 1620,1360 1636.23,1343.77 1636.23,1310.19 U3.13
MISO: ISCP.1 J10.5 pad.3@1250,1900 U3.16 | length 1922.4
  Top Layer w11.81: J10.5 1250,1870 1490,1630 1490,1361.94 U3.16 1550,1301.94 v1(1550,1270)
  Bottom Layer w11.81: v1(1550,1270) 1650,1370 2333.61,1370 ISCP.1
MOSI: ISCP.4 J10.4 pad.3@1350,1900 U3.15 | length 2114.6
  Top Layer w11.81: J10.4 1350,1870 1540,1680 1540,1392.82 1570,1362.82 v1(1570,1360) 1572.26,1357.74 1572.26,1311.17 U3.15
  Bottom Layer w11.81: v1(1570,1360) 1572.11,1360 1632.11,1420 2450,1420 2650,1220 2650,1183.38 2616.25,1149.63 2616.25,1108.83 ISCP.4
NetC8_1: C8.1 U4.4 | length 505.5
  Top Layer w11.81: C8.1 342,1197 352.09,1207.09 398.98,1207.09 461.88,1270 590,1270 v1(670,1350) ; v1(672,1412) U4.4
  Bottom Layer w11.81: v1(670,1350) 671,1351 671,1411 v1(672,1412)
NetC9_2: C9.2 U4.7 X1.1 | length 652.3
  Top Layer w11.81: U4.7 522,1552 560,1590 640,1590 705,1655 X1.1@827.91,1655 ; C9.2 794.45,1688.46 X1.1@827.91,1655 ; X1.1 X1.1@827.91,1655
NetC10_1: C10.1 U3.7 X2.1 | length 527.8
  Top Layer w11.81: U3.7 1911.74,1221.74 1997.01,1307.01 X2.1 2080,1354.01 2115.43,1389.45 C10.1
NetC11_2: C11.2 U4.8 X1.2 | length 361.5
  Top Layer w11.81: U4.8 472,1631.02 X1.2 498.1,1657.12 C11.2
NetC12_1: C12.1 U4.13 | length 558.9
  Top Layer w11.81: U4.13 672,1219.15 710,1181.15 710,1120 740,1090 740,1050 765.86,1024.14 902.23,1024.14 928.09,1050 C12.1
NetC13_1: C13.1 U3.8 X2.2 | length 646.9
  Top Layer w11.81: U3.8 1822.41,1250 v1(1860,1250) ; v1(2020,1000) 2044.57,1000 2080,964.57 X2.2 2080,930.43 2115.43,895 C13.1
  Bottom Layer w11.81: v1(1860,1250) 2020,1090 v1(2020,1000)
NetD2_2: D2.2 R1.2 | length 84.1
  Top Layer w11.81: R1.2 1137.4,1590 D2.2
NetD3_2: D3.2 R4.2 | length 84.1
  Top Layer w11.81: D3.2 1052.6,1440 R4.2
NetD4_2: D4.2 R5.2 | length 84.1
  Top Layer w11.81: D4.2 1052.6,1120 R5.2
NetD6_2: D6.2 R8.2 | length 84.1
  Top Layer w11.81: D6.2 1032.6,900 R8.2
NetQ1_1: Q1.1 U5.1 | length 1173.5
  Top Layer w11.81: Q1.1 v1(160,970) ; U5.1 v1(1155,765)
  Bottom Layer w11.81: v1(160,970) 950,970 v1(1155,765)
NetR2_1: R2.1 U4.3 | length 414
  Top Layer w11.81: v1(722,1412) U4.3 ; v1(1020,1340) R2.1
  Bottom Layer w11.81: v1(722,1412) 725.2,1412 743.2,1430 760,1430 761.72,1431.72 844.46,1431.72 936.18,1340 v1(1020,1340)
NetR3_1: R3.1 U4.2 | length 385
  Top Layer w11.81: v1(772,1412) U4.2 ; v1(1020,1260) 1042.6,1260 R3.1
  Bottom Layer w11.81: v1(772,1412) 828,1412 980,1260 v1(1020,1260)
NetR7_2: R7.2 R9.2 U5.3 | length 1260.6
  Top Layer w11.81: R7.2 R9.2 339.2,1010 v1(380,1010) ; U5.3 1102.64,660 v1(1160,660)
  Bottom Layer w11.81: v1(380,1010) 980,1010 1190,800 1190,690 v1(1160,660)
NetR8_1: R8.1 U5.6 U5.7 | length 329.4
  Top Layer w11.81: R8.1 1118.36,889.04 1118.36,851.64 1249.09,720.91 1296.46,720.91 U5.7 U5.6
RESET: C12.2 D5.2 ISCP.5 J6.3 pad.14 R6.1 SW1.3 SW1.4 U3.19 | length 4742.3
  Top Layer w11.81: SW1.4 SW1.3 360,2026.1 v1(360,1990) ; C12.2 v1(1160,1050) 1310,1050 1450.24,1190.24 U3.19 1490.95,1190.12 1599.88,1190.12 v1(1600,1190) ; J6.3 pad.14 ; v1(2260,1110) R6.1 ; v1(2370,1080) 2370,1037.91 D5.2 2467.25,1032.91 2502.07,998.1 ISCP.5
  Bottom Layer w11.81: v1(360,1990) 360,1750 580,1530 920,1530 1060,1390 1060,1202.12 1160,1102.12 v1(1160,1050) 1250,960 1250,150 J6.3 ; v1(1600,1190) 1760,1350 1950,1350 1980.28,1319.72 1980.28,1211.83 2002.12,1190 2070,1190 2110,1150 2220,1150 v1(2260,1110) 2290,1080 v1(2370,1080)
RI: J7.4 U4.11 | length 419.4
  Top Layer w11.81: U4.11 572,1246.31 578.3,1252.61 592.15,1252.61 619.53,1280 722.12,1280 751.89,1250.23 751.89,1103.11 J7.4
SCK: ISCP.3 J10.6 pad.3@1158.86,1900 U3.17 U5.5 | length 3465.4
  Top Layer w11.81: J10.6 1155,1995 1155,1905 1162.72,1897.28 1162.72,1857.28 1420,1600 1420,1280 1446.76,1253.24 U3.17 1494.06,1250 v1(1530,1250) ; v1(1269.72,620) 1274.72,615 U5.5
  Bottom Layer w11.81: v1(1269.72,620) 1269.72,649.72 1280,660 1600,660 1750,810 1750,1060 1700,1110 1630,1110 1562.05,1177.95 1562.05,1217.95 v1(1530,1250) 1530,1290 1630,1390 2392.7,1390 2560,1222.7 2560,1152.59 ISCP.3
SS: J10.3 pad.3@1450,1900 U3.14 | length 758.2
  Top Layer w11.81: J10.3 1450,1870 1580,1740 1580,1380 1605.15,1354.85 1605.15,1309.78 U3.14
UD+: J11.3 U4.5 | length 572.6
  Top Layer w11.81: v1(220,1550) 221.69,1551.69 276.73,1551.69 J11.3 ; v1(622,1412) U4.5
  Bottom Layer w11.81: v1(220,1550) 377.72,1392.28 599.96,1392.28 619.67,1412 v1(622,1412)
UD-: J11.2 U4.6 | length 554.7
  Top Layer w11.81: v1(220.94,1580.94) 274.49,1580.94 J11.2 J11.2@241.16,1584.88 ; v1(572,1412) U4.6
  Bottom Layer w11.81: v1(220.94,1580.94) 389.89,1412 v1(572,1412)
USB_5V: J11.1 PT1.1 | length 524.1
  Top Layer w11.81: PT1.1 154.38,1183.38 154.38,1542.26 225.18,1613.07 275.12,1613.07 J11.1
VIN: C5.1 D1.1 J6.8 pad.9 R7.1 U2.3 | length 2332.1
  Top Layer w11.81: R7.1 243.86,931 256.65,918.2 256.65,909.35 319.17,846.83 U2.3 379.45,790.55 v1(380,790) ; v1(580,460) 619.76,460 C5.1 630,432.83 655.59,407.24 692.76,407.24 750,350 750,240 830,160 830,98.66 827.4,96.06 911.09,12.38 1712.38,12.38 J6.8 pad.9
  Bottom Layer w11.81: v1(380,790) 580,590 v1(580,460)
pads on no net: J6.1 J11.4 J11.6 J11.7 J11.8 J11.9 J11.10 J11.11 MH1.1 MH2.1 MH3.1 MH4.1 U3.22 U3.29 U4.14 U4.15

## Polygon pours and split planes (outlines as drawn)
+5V on Top Layer "+5V_L01_P000" (solid, pour order 0): 0,0 2600,0 2600,100 2700,200 2700,1490 2600,1590 2600,2040 2540,2100 0,2100
GND on Bottom Layer "GND_L02_P001" (solid, pour order 1): 0,0 2600,0 2600,100 2700,200 2700,1490 2600,1590 2600,2040 2540,2100 0,2100

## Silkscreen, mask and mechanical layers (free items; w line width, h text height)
Top Overlay:
  drawing of 24 lines, arcs and shapes, not listed
  text "SCL" at 724.69,1843.13 h25
  text "SDA" at 827,1843.13 h25
  text "8" at 1683,1820.32 h40 r90
  text "7" at 1813,1820.32 h40 r90
  text "4" at 2113,1820.32 h40 r90
  text "2" at 2323,1820.32 h40 r90
  text "13" at 1193,1787 h40 r90
  text "12" at 1273,1787 h40 r90
  text "-9" at 1573,1780.34 h40 r90
  text "-6" at 1913,1780.34 h40 r90
  text "-5" at 2013,1780.34 h40 r90
  text "-3" at 2213,1780.34 h40 r90
  text "GND" at 1093,1777 h30 r90
  text "-11" at 1373,1777 h40 r90
  text "AREF" at 983,1757 h30 r90
  text "-10" at 1473,1757 h40 r90
  text "TX_1" at 2416.34,1713.69 h40 r90
  text "RX_0" at 2516.34,1700.36 h40 r90
  text "DIGITAL PWM (-)" at 1467,1667 h40
  text "UNO" at 1407,1457 h80
  text "RX" at 1909.33,686 h30
  text "TX" at 1989.33,686 h30
  text "5V" at 2069.33,686 h30
  text "GND" at 2144.03,686 h30
  text "SCL" at 1876,622.13 h30
  text "SDA" at 1976,622.13 h30
  text "5V" at 2074.03,622.13 h30
  text "GND" at 2144.03,622.13 h30
  text "3.3V" at 1786,556 h30
  text "3.3V" at 1916,556 h30
  text "GND" at 2046,556 h30
  text "GND" at 2144.03,556 h30
  text "POWER" at 1327,467 h40
  text "ANALOG IN" at 1757,467 h40
  text "3.3V" at 1423,260.33 h40 r90
  text "A1" at 2113,260.33 h40 r90
  text "5V" at 1233,257 h40 r90
  text "RES" at 1323,247 h40 r90
  text "5V" at 1523,247 h40 r90
  text "GND" at 1633,247 h40 r90
  text "GND" at 1733,247 h40 r90
  text "VIN" at 1823,247 h40 r90
  text "A0" at 2013,247 h40 r90
  text "A2" at 2213,247 h40 r90
  text "A3" at 2323,247 h40 r90
  text "A4" at 2423,247 h40 r90
  text "A5" at 2513,247 h40 r90
Board OutLine:
  the board outline again, w10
